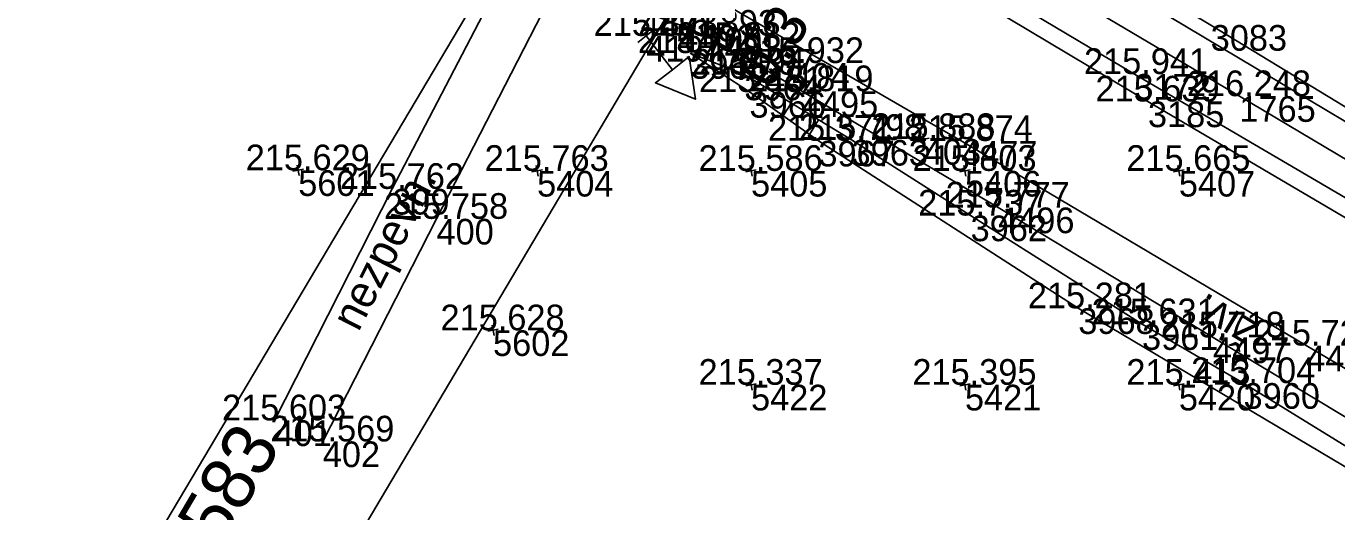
# Model space of a CAD drawing. Extents: x -556590 to -554855, y -1137918 to -1135717.
# Drawn here: x -556493.9 to -556432.6, y -1135835.9 to -1135813.2 of the extents above; entities that cross this region are included whole.
import ezdxf

# ---------------------------------------------------------------- set-up
doc = ezdxf.new("R2010")
doc.units = 0
for name, color, linetype in [('Vrstva 1', 7, 'Continuous'), ('Vrstva 4', 7, 'Continuous'), ('Vrstva 48', 7, 'Continuous'), ('Vrstva 49', 7, 'Continuous'), ('Vrstva 51', 7, 'Continuous'), ('Vrstva 60', 7, 'Continuous'), ('Vrstva 61', 7, 'Continuous'), ('Vrstva 9', 7, 'Continuous')]:
    doc.layers.add(name, color=color, linetype=linetype)

msp = doc.modelspace()

# ---------------------------------------------------------------- linework, layer by layer
at = {"layer": 'Vrstva 1'}
msp.add_lwpolyline([(-556311.953, -1135890.765), (-556321.097, -1135885.34), (-556330.284, -1135879.894), (-556339.612, -1135874.362), (-556348.582, -1135869.039), (-556357.498, -1135863.753), (-556366.106, -1135858.646), (-556374.906, -1135853.428), (-556383.234, -1135848.498), (-556391.876, -1135843.374), (-556400.908, -1135838.017), (-556409.759, -1135832.769), (-556418.646, -1135827.5), (-556428.018, -1135821.939), (-556437.172, -1135816.507), (-556446.468, -1135810.997), (-556456.022, -1135805.326), (-556463.479, -1135800.909), (-556467.629, -1135798.446), (-556476.522, -1135793.164), (-556485.71, -1135787.715), (-556494.622, -1135782.427), (-556503.989, -1135776.868), (-556513.289, -1135771.345)], dxfattribs=at)
at = {"layer": 'Vrstva 4'}
msp.add_line((-556465.554, -1135799.678), (-556496.177, -1135851.275), dxfattribs=at)
for points in [[(-556423.133, -1135823.118), (-556442.147, -1135811.755), (-556461.606, -1135800.09), (-556462.261, -1135799.671), (-556462.556, -1135799.308), (-556462.656, -1135799.127), (-556461.963, -1135799.074), (-556461.506, -1135799.244), (-556450.518, -1135806.011), (-556438.512, -1135813.182), (-556425.945, -1135820.823)], [(-556429.315, -1135822.957), (-556442.078, -1135815.472), (-556456.395, -1135806.956), (-556460.94, -1135804.337), (-556461.836, -1135803.803), (-556462.329, -1135803.606), (-556462.774, -1135803.562), (-556462.023, -1135804.323), (-556461.425, -1135804.873), (-556460.663, -1135805.387), (-556457.875, -1135806.855), (-556455.835, -1135808.089), (-556454.489, -1135808.903), (-556452.58, -1135810.098), (-556441.444, -1135816.756), (-556425.052, -1135826.406)]]:
    msp.add_lwpolyline(points, dxfattribs=at)
at = {"layer": 'Vrstva 48'}
for p, q in [((-556459.405, -1135816.049), (-556459.718, -1135816.562)), ((-556458.765, -1135816.439), (-556458.935, -1135816.718)), ((-556458.124, -1135816.83), (-556458.491, -1135817.431)), ((-556457.484, -1135817.221), (-556457.681, -1135817.543)), ((-556456.844, -1135817.611), (-556457.264, -1135818.3))]:
    msp.add_line(p, q, dxfattribs=at)
at = {"layer": 'Vrstva 49'}
for p, q in [((-556457.826, -1135814.911), (-556458.318, -1135815.005)), ((-556458.119, -1135814.712), (-556458.025, -1135815.204)), ((-556451.677, -1135818.465), (-556452.169, -1135818.559)), ((-556451.97, -1135818.266), (-556451.876, -1135818.758)), ((-556480.921, -1135819.925), (-556481.413, -1135820.019)), ((-556481.214, -1135819.726), (-556481.12, -1135820.218)), ((-556469.754, -1135819.953), (-556470.246, -1135820.047)), ((-556470.047, -1135819.754), (-556469.953, -1135820.246)), ((-556459.754, -1135819.953), (-556460.246, -1135820.047)), ((-556460.047, -1135819.754), (-556459.953, -1135820.246)), ((-556449.754, -1135819.953), (-556450.246, -1135820.047)), ((-556450.047, -1135819.754), (-556449.953, -1135820.246)), ((-556439.754, -1135819.953), (-556440.246, -1135820.047)), ((-556440.047, -1135819.754), (-556439.953, -1135820.246)), ((-556472.108, -1135827.207), (-556472.014, -1135827.699)), ((-556471.815, -1135827.406), (-556472.307, -1135827.5)), ((-556460.047, -1135829.754), (-556459.953, -1135830.246)), ((-556450.047, -1135829.754), (-556449.953, -1135830.246)), ((-556440.047, -1135829.754), (-556439.953, -1135830.246)), ((-556459.754, -1135829.953), (-556460.246, -1135830.047)), ((-556449.754, -1135829.953), (-556450.246, -1135830.047)), ((-556439.754, -1135829.953), (-556440.246, -1135830.047))]:
    msp.add_line(p, q, dxfattribs=at)
for points in [[(-556314.511, -1135904.668), (-556319.895, -1135900.763), (-556331.506, -1135892.959), (-556347.837, -1135882.719), (-556362.357, -1135874.245), (-556375.408, -1135866.289), (-556386.305, -1135859.951), (-556395.432, -1135854.82), (-556408.821, -1135846.814), (-556423.881, -1135837.997), (-556436.976, -1135829.922), (-556441.721, -1135827.169), (-556449.734, -1135822.087), (-556455.301, -1135818.553), (-556460.309, -1135815.497), (-556462.838, -1135814.492)], [(-556462.838, -1135814.492), (-556460.072, -1135816.311), (-556456.85, -1135818.594), (-556444.702, -1135826.423), (-556426.707, -1135837.111), (-556413.147, -1135845.027), (-556398.896, -1135853.568), (-556384.898, -1135861.872), (-556372.023, -1135869.441), (-556359.246, -1135876.906), (-556344.292, -1135885.842), (-556334.57, -1135891.963), (-556325.907, -1135897.778), (-556317.723, -1135903.094), (-556310.891, -1135907.723)]]:
    msp.add_lwpolyline(points, dxfattribs=at)
at = {"layer": 'Vrstva 51'}
msp.add_line((-556464.507, -1135813.382), (-556465.297, -1135813.996), dxfattribs=at)
for points in [[(-556427.652, -1135834.25), (-556438.402, -1135827.787), (-556448.45, -1135821.713), (-556457.623, -1135816.274), (-556461.051, -1135814.258), (-556462.132, -1135813.683), (-556463.351, -1135813.175), (-556465.172, -1135812.525), (-556466.811, -1135811.903), (-556468.873, -1135810.882), (-556472.215, -1135808.962), (-556473.2, -1135808.424), (-556476.103, -1135806.706), (-556480.169, -1135804.315), (-556485.388, -1135801.272), (-556492.788, -1135796.819), (-556506.842, -1135788.616), (-556517.117, -1135782.94)], [(-556311.659, -1135902.566), (-556322.953, -1135895.006), (-556333.382, -1135888.324), (-556345.392, -1135880.784), (-556355.743, -1135874.358), (-556370.294, -1135865.79), (-556386.065, -1135856.415), (-556403.078, -1135846.377), (-556420.094, -1135836.387), (-556434.047, -1135828.164), (-556450.177, -1135818.6), (-556462.863, -1135811.247), (-556468.08, -1135808.062), (-556470.037, -1135806.838), (-556473.202, -1135805.131)], [(-556482.276, -1135831.663), (-556476.77, -1135820.842), (-556472.149, -1135811.941), (-556472.215, -1135808.962)], [(-556480.02, -1135832.65), (-556474.703, -1135822.242), (-556468.873, -1135810.882)], [(-556464.902, -1135813.689), (-556463.676, -1135815.269), (-556464.466, -1135815.882), (-556462.603, -1135816.652), (-556462.886, -1135814.656), (-556463.676, -1135815.269)]]:
    msp.add_lwpolyline(points, dxfattribs=at)
at = {"layer": 'Vrstva 60'}
for p, q in [((-556464.902, -1135813.689), (-556464.902, -1135813.689)), ((-556462.132, -1135813.683), (-556462.132, -1135813.683)), ((-556462.838, -1135814.492), (-556462.838, -1135814.492)), ((-556461.051, -1135814.258), (-556461.051, -1135814.258)), ((-556458.072, -1135814.958), (-556458.072, -1135814.958)), ((-556460.309, -1135815.497), (-556460.309, -1135815.497)), ((-556442.078, -1135815.472), (-556442.078, -1135815.472)), ((-556460.072, -1135816.311), (-556460.072, -1135816.311)), ((-556457.623, -1135816.274), (-556457.623, -1135816.274)), ((-556441.444, -1135816.756), (-556441.444, -1135816.756)), ((-556437.172, -1135816.507), (-556437.172, -1135816.507)), ((-556456.85, -1135818.594), (-556456.85, -1135818.594)), ((-556455.301, -1135818.553), (-556455.301, -1135818.553)), ((-556451.923, -1135818.512), (-556451.923, -1135818.512)), ((-556450.177, -1135818.6), (-556450.177, -1135818.6)), ((-556481.167, -1135819.972), (-556481.167, -1135819.972)), ((-556470, -1135820), (-556470, -1135820)), ((-556460, -1135820), (-556460, -1135820)), ((-556450, -1135820), (-556450, -1135820)), ((-556440, -1135820), (-556440, -1135820)), ((-556476.77, -1135820.842), (-556476.77, -1135820.842)), ((-556448.45, -1135821.713), (-556448.45, -1135821.713)), ((-556474.703, -1135822.242), (-556474.703, -1135822.242)), ((-556449.734, -1135822.087), (-556449.734, -1135822.087)), ((-556444.702, -1135826.423), (-556444.702, -1135826.423)), ((-556441.721, -1135827.169), (-556441.721, -1135827.169)), ((-556472.061, -1135827.453), (-556472.061, -1135827.453)), ((-556438.402, -1135827.787), (-556438.402, -1135827.787)), ((-556434.047, -1135828.164), (-556434.047, -1135828.164)), ((-556460, -1135830), (-556460, -1135830)), ((-556450, -1135830), (-556450, -1135830)), ((-556440, -1135830), (-556440, -1135830)), ((-556436.976, -1135829.922), (-556436.976, -1135829.922)), ((-556482.276, -1135831.663), (-556482.276, -1135831.663)), ((-556480.02, -1135832.65), (-556480.02, -1135832.65))]:
    msp.add_line(p, q, dxfattribs=at)
at = {"layer": 'Vrstva 9'}
msp.add_line((-556460.05, -1135806.202), (-556490.638, -1135857.807), dxfattribs=at)

# ---------------------------------------------------------------- texts
at = {"layer": 'Vrstva 4'}
msp.add_text('evid. km 78,583', height=2.5, rotation=59.5055, dxfattribs=at).set_placement((-556493.928, -1135853.191))
at = {"layer": 'Vrstva 48'}
msp.add_text('0,3', height=2, rotation=58.60747, dxfattribs=at).set_placement((-556459.114, -1135816.267))
at = {"layer": 'Vrstva 51'}
for s, rotation, p in [('nezpevn.', 62.93946, (-556478.35, -1135827.564)), ('živ.', 148.8471, (-556436.185, -1135827.198))]:
    msp.add_text(s, height=1.5, rotation=rotation, dxfattribs=at).set_placement(p)
at = {"layer": 'Vrstva 60'}
for s, p in [('4491', (-556465.172, -1135813.725)), ('4492', (-556463.351, -1135814.375)), ('3083', (-556438.512, -1135814.382)), ('4197', (-556464.902, -1135814.889)), ('4493', (-556462.132, -1135814.883)), ('3965', (-556462.838, -1135815.692)), ('4494', (-556461.051, -1135815.458)), ('404', (-556458.072, -1135816.158)), ('3964', (-556460.309, -1135816.697)), ('3172', (-556442.078, -1135816.672)), ('3966', (-556460.072, -1135817.511)), ('4495', (-556457.623, -1135817.474)), ('3185', (-556441.444, -1135817.956)), ('1765', (-556437.172, -1135817.707)), ('3967', (-556456.85, -1135819.794)), ('3963', (-556455.301, -1135819.753)), ('403', (-556451.923, -1135819.712)), ('4477', (-556450.177, -1135819.8)), ('5601', (-556481.167, -1135821.172)), ('5404', (-556470, -1135821.2)), ('5405', (-556460, -1135821.2)), ('5406', (-556450, -1135821.2)), ('5407', (-556440, -1135821.2)), ('399', (-556476.77, -1135822.042)), ('4496', (-556448.45, -1135822.913)), ('400', (-556474.703, -1135823.442)), ('3962', (-556449.734, -1135823.287)), ('3968', (-556444.702, -1135827.623)), ('3961', (-556441.721, -1135828.369)), ('5602', (-556472.061, -1135828.653)), ('4497', (-556438.402, -1135828.987)), ('4476', (-556434.047, -1135829.364)), ('5422', (-556460, -1135831.2)), ('5421', (-556450, -1135831.2)), ('5420', (-556440, -1135831.2)), ('3960', (-556436.976, -1135831.122)), ('401', (-556482.276, -1135832.863)), ('402', (-556480.02, -1135833.85))]:
    msp.add_text(s, height=1.2, dxfattribs=at).set_placement(p)
at = {"layer": 'Vrstva 61'}
for s, p in [('215.878', (-556467.356, -1135813.689)), ('215.893', (-556464.584, -1135813.683)), ('215.700', (-556465.289, -1135814.492)), ('215.882', (-556463.499, -1135814.258)), ('215.932', (-556460.52, -1135814.958)), ('215.797', (-556462.761, -1135815.497)), ('215.941', (-556444.435, -1135815.472)), ('215.481', (-556462.429, -1135816.311)), ('215.819', (-556460.077, -1135816.274)), ('215.639', (-556443.898, -1135816.756)), ('216.248', (-556439.626, -1135816.507)), ('215.371', (-556459.207, -1135818.594)), ('215.798', (-556457.755, -1135818.553)), ('215.888', (-556454.377, -1135818.512)), ('215.874', (-556452.628, -1135818.6)), ('215.629', (-556483.621, -1135819.972)), ('215.763', (-556472.452, -1135820)), ('215.586', (-556462.452, -1135820)), ('215.803', (-556452.452, -1135820)), ('215.665', (-556442.456, -1135820)), ('215.762', (-556479.218, -1135820.842)), ('215.777', (-556450.902, -1135821.713)), ('215.758', (-556477.157, -1135822.242)), ('215.737', (-556452.186, -1135822.087)), ('215.281', (-556447.059, -1135826.423)), ('215.631', (-556444.078, -1135827.169)), ('215.628', (-556474.515, -1135827.453)), ('215.718', (-556440.856, -1135827.787)), ('215.728', (-556436.501, -1135828.164)), ('215.337', (-556462.452, -1135830)), ('215.395', (-556452.456, -1135830)), ('215.413', (-556442.452, -1135830)), ('215.704', (-556439.427, -1135829.922)), ('215.603', (-556484.728, -1135831.663)), ('215.569', (-556482.474, -1135832.65))]:
    msp.add_text(s, height=1.2, dxfattribs=at).set_placement(p)

doc.saveas('drawing.dxf')
